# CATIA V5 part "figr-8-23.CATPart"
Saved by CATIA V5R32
Part number: Part1
Bounding box of the stored display mesh (mm): x -50 to 50, y -62.5 to 62.5, z 0 to 10
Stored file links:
  D:\PROJECTS\Project 2022\CATIA V5 6R 2022\Resources\Part Files\c08_catia_v5_6r2022_prt\figr-8-23.CATPart
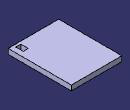
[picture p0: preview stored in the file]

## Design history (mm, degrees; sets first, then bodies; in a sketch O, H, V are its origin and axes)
Body1 (main body)
  Sketch1 on xy-plane, origin (0, 0, 0), H (1, 0, 0), V (0, 1, 0)
    line L1 (-50, 62.5) -> (50, 62.5)
    line L2 (50, 62.5) -> (50, -62.5)
    line L3 (50, -62.5) -> (-50, -62.5)
    line L4 (-50, -62.5) -> (-50, 62.5)
    axis line L5 (50, -62.5) -> (-50, 62.5)
    length L3 = 100
    length L2 = 125
    horizontal: L1 H, L3 H
    vertical: L2 V, L4 V
    midpoint: O L5
  Pad1: profile Sketch1, direction (0, 0, 1), length 10
  Sketch2 on face of Pad1, origin (0, 0, 10), H (1, 0, 0), V (0, 1, 0)
    line L1 (40, -57.5) -> (30, -57.5)
    line L2 (30, -57.5) -> (30, -42.5)
    line L3 (30, -42.5) -> (40, -42.5)
    line L4 (40, -42.5) -> (40, -57.5)
    reference projected line E1 (-50, -62.5) -> (50, -62.5) from edge [face of Pad1 | face of Pad1]
    reference projected line E2 (50, -62.5) -> (50, 62.5) from edge [face of Pad1 | face of Pad1]
    length L1 = 10
    length L4 = 15
    distance L1 E1 = 5
    distance L4 E2 = 10
    horizontal: L1 H, L3 H
    vertical: L2 V, L4 V
  Pocket1: profile Sketch2, direction (0, 0, -1), through (limit type 3)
